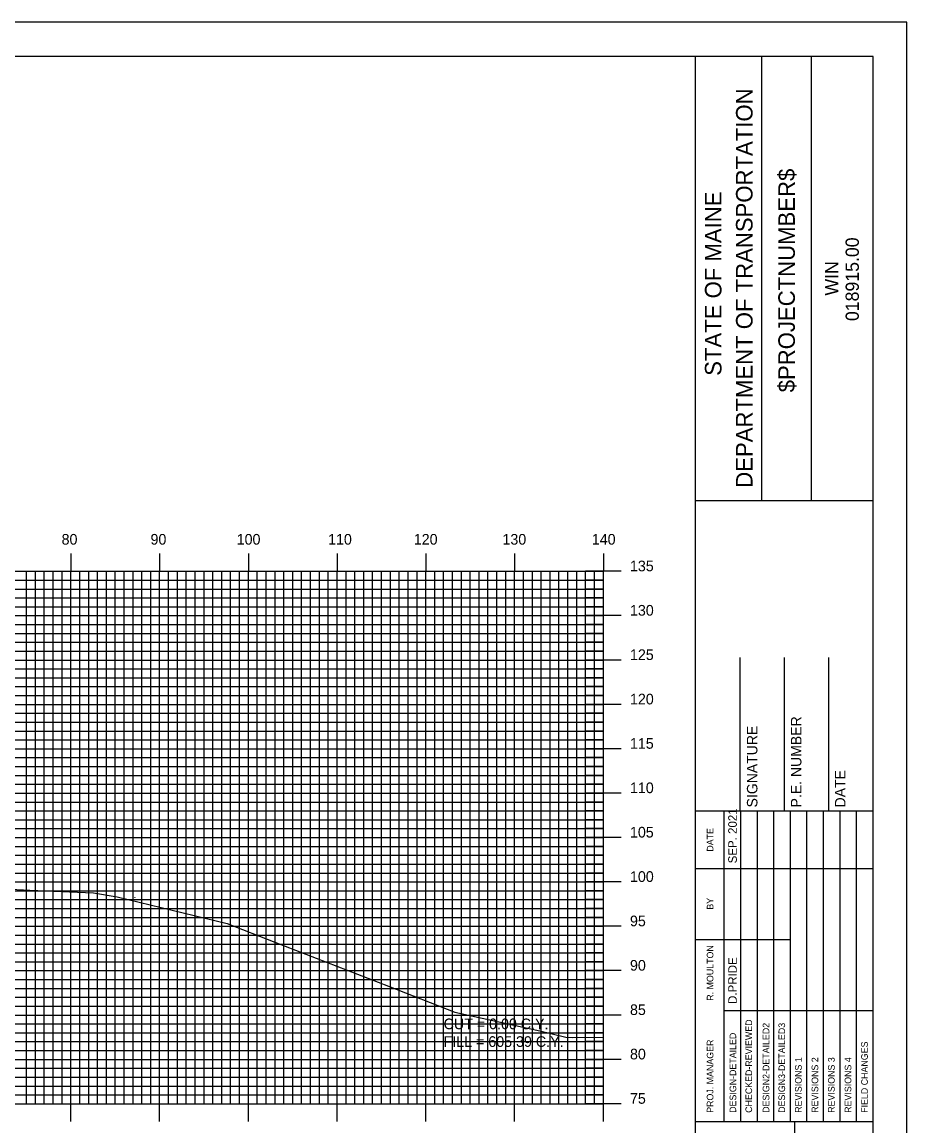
# Model space of a CAD drawing. Extents: x 857265 to 857608, y 364366 to 364586.
# Drawn here: x 857504.8 to 857604.5, y 364461.3 to 364585.7 of the extents above; entities that cross this region are included whole.
import ezdxf

# ---------------------------------------------------------------- set-up
doc = ezdxf.new("R2010")
doc.units = 0
for name, color, linetype in [('BORDER', 7, 'Continuous'), ('D_Text_Standard', 7, 'Continuous'), ('H_V ANNOTATION', 7, 'Continuous'), ('M_Utilities_Pole', 7, 'Continuous'), ('MAJOR', 7, 'Continuous'), ('MINOR', 7, 'Continuous'), ('PLOT BOUNDARY', 7, 'Continuous'), ('S_Roadway_Centerline', 7, 'Continuous')]:
    doc.layers.add(name, color=color, linetype=linetype)

msp = doc.modelspace()

# ---------------------------------------------------------------- linework, layer by layer
at = {"layer": 'BORDER'}
for p, q in [((857580.74, 364371.79), (857580.74, 364581.79)), ((857588.19, 364531.78), (857588.19, 364581.78)), ((857593.78, 364531.78), (857593.78, 364581.78)), ((857580.74, 364531.78), (857600.74, 364531.78)), ((857585.74, 364496.79), (857585.74, 364514.09)), ((857590.74, 364496.79), (857590.74, 364514.09)), ((857595.74, 364496.79), (857595.74, 364514.09)), ((857580.74, 364496.79), (857600.74, 364496.79)), ((857580.74, 364461.79), (857600.74, 364461.79)), ((857591.92, 364391.79), (857591.92, 364461.79))]:
    msp.add_line(p, q, dxfattribs=at)
msp.add_lwpolyline([(857280.74, 364371.79), (857600.74, 364371.79), (857600.74, 364581.79), (857280.74, 364581.79)], close=True, dxfattribs=at)
for points in [[(857583.97, 364490.29), (857583.97, 364496.79)], [(857585.83, 364461.8), (857585.83, 364496.79)], [(857587.69, 364496.79), (857587.69, 364461.8)], [(857589.56, 364461.8), (857589.56, 364496.79)], [(857591.42, 364461.8), (857591.42, 364496.79)], [(857593.28, 364461.8), (857593.28, 364496.79)], [(857595.15, 364461.8), (857595.15, 364496.79)], [(857597.01, 364461.8), (857597.01, 364496.79)], [(857598.87, 364461.8), (857598.87, 364496.79)], [(857583.97, 364461.8), (857583.97, 364495.38)], [(857580.74, 364490.29), (857600.74, 364490.29)], [(857580.74, 364482.29), (857583.97, 364482.29)], [(857583.97, 364482.29), (857591.42, 364482.29)], [(857583.97, 364474.29), (857600.74, 364474.29)]]:
    msp.add_lwpolyline(points, dxfattribs=at)
at = {"layer": 'M_Utilities_Pole'}
msp.add_line((857517.53, 364487.05), (857517.53, 364487.04), dxfattribs=at)
msp.add_circle((857517.53, 364487.05), 0.00417, dxfattribs=at)
at = {"layer": 'MAJOR'}
for p, q in [((857510.34, 364525.79), (857510.34, 364523.79)), ((857520.34, 364525.79), (857520.34, 364523.79)), ((857530.34, 364525.79), (857530.34, 364523.79)), ((857540.34, 364525.79), (857540.34, 364523.79)), ((857550.34, 364525.79), (857550.34, 364523.79)), ((857560.34, 364525.79), (857560.34, 364523.79)), ((857570.34, 364525.79), (857570.34, 364523.79)), ((857290.34, 364523.79), (857570.34, 364523.79)), ((857290.34, 364523.79), (857570.34, 364523.79)), ((857510.34, 364463.79), (857510.34, 364523.79)), ((857520.34, 364463.79), (857520.34, 364523.79)), ((857530.34, 364463.79), (857530.34, 364523.79)), ((857540.34, 364463.79), (857540.34, 364523.79)), ((857550.34, 364463.79), (857550.34, 364523.79)), ((857560.34, 364463.79), (857560.34, 364523.79)), ((857572.34, 364523.79), (857568.33, 364523.79)), ((857570.34, 364463.79), (857570.34, 364523.79)), ((857570.34, 364463.79), (857570.34, 364523.79)), ((857290.34, 364518.79), (857570.34, 364518.79)), ((857572.34, 364518.79), (857568.33, 364518.79)), ((857290.34, 364513.79), (857570.34, 364513.79)), ((857572.34, 364513.79), (857568.33, 364513.79)), ((857290.34, 364508.79), (857570.34, 364508.79)), ((857572.34, 364508.79), (857568.33, 364508.79)), ((857290.34, 364503.79), (857570.34, 364503.79)), ((857572.34, 364503.79), (857568.33, 364503.79)), ((857290.34, 364498.79), (857570.34, 364498.79)), ((857572.34, 364498.79), (857568.33, 364498.79)), ((857290.34, 364493.79), (857570.34, 364493.79)), ((857572.34, 364493.79), (857568.33, 364493.79)), ((857290.34, 364488.79), (857570.34, 364488.79)), ((857572.34, 364488.79), (857568.33, 364488.79)), ((857290.34, 364483.79), (857570.34, 364483.79)), ((857572.34, 364483.79), (857568.33, 364483.79)), ((857290.34, 364478.79), (857570.34, 364478.79)), ((857572.34, 364478.79), (857568.33, 364478.79)), ((857290.34, 364473.79), (857570.34, 364473.79)), ((857572.34, 364473.79), (857568.33, 364473.79)), ((857290.34, 364468.79), (857570.34, 364468.79)), ((857572.34, 364468.79), (857568.33, 364468.79)), ((857290.34, 364463.79), (857570.34, 364463.79)), ((857290.34, 364463.79), (857570.34, 364463.79)), ((857510.34, 364461.78), (857510.34, 364463.79)), ((857520.34, 364461.78), (857520.34, 364463.79)), ((857530.34, 364461.78), (857530.34, 364463.79)), ((857540.34, 364461.78), (857540.34, 364463.79)), ((857550.34, 364461.78), (857550.34, 364463.79)), ((857560.34, 364461.78), (857560.34, 364463.79)), ((857572.34, 364463.79), (857568.33, 364463.79)), ((857570.34, 364461.78), (857570.34, 364463.79))]:
    msp.add_line(p, q, dxfattribs=at)
at = {"layer": 'MINOR'}
for p, q in [((857290.34, 364522.79), (857570.34, 364522.79)), ((857505.34, 364463.79), (857505.34, 364523.79)), ((857506.34, 364463.79), (857506.34, 364523.79)), ((857507.34, 364463.79), (857507.34, 364523.79)), ((857508.34, 364463.79), (857508.34, 364523.79)), ((857509.34, 364463.79), (857509.34, 364523.79)), ((857511.34, 364463.79), (857511.34, 364523.79)), ((857512.34, 364463.79), (857512.34, 364523.79)), ((857513.34, 364463.79), (857513.34, 364523.79)), ((857514.34, 364463.79), (857514.34, 364523.79)), ((857515.34, 364463.79), (857515.34, 364523.79)), ((857516.34, 364463.79), (857516.34, 364523.79)), ((857517.34, 364463.79), (857517.34, 364523.79)), ((857518.34, 364463.79), (857518.34, 364523.79)), ((857519.34, 364463.79), (857519.34, 364523.79)), ((857521.34, 364463.79), (857521.34, 364523.79)), ((857522.34, 364463.79), (857522.34, 364523.79)), ((857523.34, 364463.79), (857523.34, 364523.79)), ((857524.34, 364463.79), (857524.34, 364523.79)), ((857525.34, 364463.79), (857525.34, 364523.79)), ((857526.34, 364463.79), (857526.34, 364523.79)), ((857527.34, 364463.79), (857527.34, 364523.79)), ((857528.34, 364463.79), (857528.34, 364523.79)), ((857529.34, 364463.79), (857529.34, 364523.79)), ((857531.34, 364463.79), (857531.34, 364523.79)), ((857532.34, 364463.79), (857532.34, 364523.79)), ((857533.34, 364463.79), (857533.34, 364523.79)), ((857534.34, 364463.79), (857534.34, 364523.79)), ((857535.34, 364463.79), (857535.34, 364523.79)), ((857536.34, 364463.79), (857536.34, 364523.79)), ((857537.34, 364463.79), (857537.34, 364523.79)), ((857538.34, 364463.79), (857538.34, 364523.79)), ((857539.34, 364463.79), (857539.34, 364523.79)), ((857541.34, 364463.79), (857541.34, 364523.79)), ((857542.34, 364463.79), (857542.34, 364523.79)), ((857543.34, 364463.79), (857543.34, 364523.79)), ((857544.34, 364463.79), (857544.34, 364523.79)), ((857545.34, 364463.79), (857545.34, 364523.79)), ((857546.34, 364463.79), (857546.34, 364523.79)), ((857547.34, 364463.79), (857547.34, 364523.79)), ((857548.34, 364463.79), (857548.34, 364523.79)), ((857549.34, 364463.79), (857549.34, 364523.79)), ((857551.34, 364463.79), (857551.34, 364523.79)), ((857552.34, 364463.79), (857552.34, 364523.79)), ((857553.34, 364463.79), (857553.34, 364523.79)), ((857554.34, 364463.79), (857554.34, 364523.79)), ((857555.34, 364463.79), (857555.34, 364523.79)), ((857556.34, 364463.79), (857556.34, 364523.79)), ((857557.34, 364463.79), (857557.34, 364523.79)), ((857558.34, 364463.79), (857558.34, 364523.79)), ((857559.34, 364463.79), (857559.34, 364523.79)), ((857561.34, 364463.79), (857561.34, 364523.79)), ((857562.34, 364463.79), (857562.34, 364523.79)), ((857563.34, 364463.79), (857563.34, 364523.79)), ((857564.34, 364463.79), (857564.34, 364523.79)), ((857565.34, 364463.79), (857565.34, 364523.79)), ((857566.34, 364463.79), (857566.34, 364523.79)), ((857567.34, 364463.79), (857567.34, 364523.79)), ((857570.34, 364522.79), (857568.33, 364522.79)), ((857568.34, 364463.79), (857568.34, 364523.79)), ((857569.34, 364463.79), (857569.34, 364523.79)), ((857290.34, 364521.79), (857570.34, 364521.79)), ((857570.34, 364521.79), (857568.33, 364521.79)), ((857290.34, 364520.79), (857570.34, 364520.79)), ((857570.34, 364520.79), (857568.33, 364520.79)), ((857290.34, 364519.79), (857570.34, 364519.79)), ((857570.34, 364519.79), (857568.33, 364519.79)), ((857290.34, 364517.79), (857570.34, 364517.79)), ((857570.34, 364517.79), (857568.33, 364517.79)), ((857290.34, 364516.79), (857570.34, 364516.79)), ((857570.34, 364516.79), (857568.33, 364516.79)), ((857290.34, 364515.79), (857570.34, 364515.79)), ((857570.34, 364515.79), (857568.33, 364515.79)), ((857290.34, 364514.79), (857570.34, 364514.79)), ((857570.34, 364514.79), (857568.33, 364514.79)), ((857290.34, 364512.79), (857570.34, 364512.79)), ((857570.34, 364512.79), (857568.33, 364512.79)), ((857290.34, 364511.79), (857570.34, 364511.79)), ((857570.34, 364511.79), (857568.33, 364511.79)), ((857290.34, 364510.79), (857570.34, 364510.79)), ((857570.34, 364510.79), (857568.33, 364510.79)), ((857290.34, 364509.79), (857570.34, 364509.79)), ((857570.34, 364509.79), (857568.33, 364509.79)), ((857290.34, 364507.79), (857570.34, 364507.79)), ((857570.34, 364507.79), (857568.33, 364507.79)), ((857290.34, 364506.79), (857570.34, 364506.79)), ((857570.34, 364506.79), (857568.33, 364506.79)), ((857290.34, 364505.79), (857570.34, 364505.79)), ((857570.34, 364505.79), (857568.33, 364505.79)), ((857290.34, 364504.79), (857570.34, 364504.79)), ((857570.34, 364504.79), (857568.33, 364504.79)), ((857290.34, 364502.79), (857570.34, 364502.79)), ((857570.34, 364502.79), (857568.33, 364502.79)), ((857290.34, 364501.79), (857570.34, 364501.79)), ((857570.34, 364501.79), (857568.33, 364501.79)), ((857290.34, 364500.79), (857570.34, 364500.79)), ((857570.34, 364500.79), (857568.33, 364500.79)), ((857290.34, 364499.79), (857570.34, 364499.79)), ((857570.34, 364499.79), (857568.33, 364499.79)), ((857290.34, 364497.79), (857570.34, 364497.79)), ((857570.34, 364497.79), (857568.33, 364497.79)), ((857290.34, 364496.79), (857570.34, 364496.79)), ((857570.34, 364496.79), (857568.33, 364496.79)), ((857290.34, 364495.79), (857570.34, 364495.79)), ((857570.34, 364495.79), (857568.33, 364495.79)), ((857290.34, 364494.79), (857570.34, 364494.79)), ((857570.34, 364494.79), (857568.33, 364494.79)), ((857290.34, 364492.79), (857570.34, 364492.79)), ((857570.34, 364492.79), (857568.33, 364492.79)), ((857290.34, 364491.79), (857570.34, 364491.79)), ((857570.34, 364491.79), (857568.33, 364491.79)), ((857290.34, 364490.79), (857570.34, 364490.79)), ((857570.34, 364490.79), (857568.33, 364490.79)), ((857290.34, 364489.79), (857570.34, 364489.79)), ((857570.34, 364489.79), (857568.33, 364489.79)), ((857290.34, 364487.79), (857570.34, 364487.79)), ((857570.34, 364487.79), (857568.33, 364487.79)), ((857290.34, 364486.79), (857570.34, 364486.79)), ((857570.34, 364486.79), (857568.33, 364486.79)), ((857290.34, 364485.79), (857570.34, 364485.79)), ((857570.34, 364485.79), (857568.33, 364485.79)), ((857290.34, 364484.79), (857570.34, 364484.79)), ((857570.34, 364484.79), (857568.33, 364484.79)), ((857290.34, 364482.79), (857570.34, 364482.79)), ((857570.34, 364482.79), (857568.33, 364482.79)), ((857290.34, 364481.79), (857570.34, 364481.79)), ((857570.34, 364481.79), (857568.33, 364481.79)), ((857290.34, 364480.79), (857570.34, 364480.79)), ((857570.34, 364480.79), (857568.33, 364480.79)), ((857290.34, 364479.79), (857570.34, 364479.79)), ((857570.34, 364479.79), (857568.33, 364479.79)), ((857290.34, 364477.79), (857570.34, 364477.79)), ((857570.34, 364477.79), (857568.33, 364477.79)), ((857290.34, 364476.79), (857570.34, 364476.79)), ((857570.34, 364476.79), (857568.33, 364476.79)), ((857290.34, 364475.79), (857570.34, 364475.79)), ((857570.34, 364475.79), (857568.33, 364475.79)), ((857290.34, 364474.79), (857570.34, 364474.79)), ((857570.34, 364474.79), (857568.33, 364474.79)), ((857290.34, 364472.79), (857570.34, 364472.79)), ((857290.34, 364471.79), (857570.34, 364471.79)), ((857570.34, 364472.79), (857568.33, 364472.79)), ((857570.34, 364471.79), (857568.33, 364471.79)), ((857290.34, 364470.79), (857570.34, 364470.79)), ((857570.34, 364470.79), (857568.33, 364470.79)), ((857290.34, 364469.79), (857570.34, 364469.79)), ((857570.34, 364469.79), (857568.33, 364469.79)), ((857290.34, 364467.79), (857570.34, 364467.79)), ((857290.34, 364466.79), (857570.34, 364466.79)), ((857570.34, 364467.79), (857568.33, 364467.79)), ((857570.34, 364466.79), (857568.33, 364466.79)), ((857290.34, 364465.79), (857570.34, 364465.79)), ((857570.34, 364465.79), (857568.33, 364465.79)), ((857290.34, 364464.79), (857570.34, 364464.79)), ((857570.34, 364464.79), (857568.33, 364464.79))]:
    msp.add_line(p, q, dxfattribs=at)
at = {"layer": 'PLOT BOUNDARY'}
msp.add_lwpolyline([(857264.55, 364365.67), (857604.55, 364365.67), (857604.55, 364585.67), (857264.55, 364585.67)], close=True, dxfattribs=at)
at = {"layer": 'S_Roadway_Centerline'}
msp.add_lwpolyline([(857498.39, 364488.22), (857505.71, 364487.85), (857512.88, 364487.57), (857515.56, 364487.11), (857527.94, 364484.12), (857533.32, 364481.98), (857546.14, 364477.05), (857553.6, 364474.1), (857563.17, 364472.02), (857566.1, 364471.29), (857566.85, 364471.27), (857568.31, 364471.28), (857570.34, 364471.25)], dxfattribs=at)

# ---------------------------------------------------------------- texts
at = {"layer": 'BORDER'}
for s, height, p in [('DEPARTMENT OF TRANSPORTATION', 1.8635, (857587.15, 364533.2)), ('$PROJECTNUMBER$', 1.8635, (857591.92, 364543.95)), ('STATE OF MAINE', 1.8635, (857583.65, 364545.81)), ('018915.00', 1.491, (857599.13, 364551.98)), ('WIN', 1.491, (857596.81, 364554.85)), ('P.E. NUMBER', 1.1811, (857592.66, 364497.18)), ('SIGNATURE', 1.181, (857587.7, 364497.18)), ('DATE', 1.181, (857597.62, 364497.18)), ('SEP. 2021', 0.969, (857585.38, 364490.88)), ('DATE', 0.743, (857582.74, 364492.2)), ('BY', 0.743, (857582.74, 364485.66)), ('R. MOULTON', 0.745, (857582.74, 364475.4)), ('D.PRIDE', 0.969, (857585.38, 364475.04)), ('CHECKED-REVIEWED', 0.7455, (857587.1, 364462.77)), ('DESIGN2-DETAILED2', 0.7455, (857589.04, 364462.77)), ('DESIGN3-DETAILED3', 0.7455, (857590.82, 364462.77)), ('DESIGN-DETAILED', 0.7455, (857585.31, 364462.77)), ('PROJ. MANAGER', 0.7455, (857582.74, 364462.77)), ('FIELD CHANGES', 0.7455, (857600.14, 364462.77)), ('REVISIONS 1', 0.7455, (857592.69, 364462.77)), ('REVISIONS 2', 0.7455, (857594.55, 364462.77)), ('REVISIONS 3', 0.7455, (857596.41, 364462.77)), ('REVISIONS 4', 0.7455, (857598.28, 364462.77))]:
    msp.add_text(s, height=height, rotation=90, dxfattribs=at).set_placement(p)
at = {"layer": 'D_Text_Standard'}
for s, p in [('CUT = 0.00 C.Y.', (857552.34, 364472.19)), ('FILL = 605.39 C.Y.', (857552.34, 364470.2))]:
    msp.add_text(s, height=1.2, dxfattribs=at).set_placement(p)
at = {"layer": 'H_V ANNOTATION'}
for s, p in [('80', (857509.29, 364526.79)), ('90', (857519.31, 364526.79)), ('100', (857529.02, 364526.79)), ('110', (857539.32, 364526.79)), ('120', (857548.98, 364526.79)), ('130', (857558.97, 364526.79)), ('140', (857569.04, 364526.79)), ('135', (857573.34, 364523.79)), ('130', (857573.34, 364518.79)), ('125', (857573.34, 364513.79)), ('120', (857573.34, 364508.79)), ('115', (857573.34, 364503.79)), ('110', (857573.34, 364498.79)), ('105', (857573.34, 364493.79)), ('100', (857573.34, 364488.79)), ('95', (857573.34, 364483.79)), ('90', (857573.34, 364478.79)), ('85', (857573.34, 364473.79)), ('80', (857573.34, 364468.79)), ('75', (857573.34, 364463.79))]:
    msp.add_text(s, height=1.2, dxfattribs=at).set_placement(p)

doc.saveas('drawing.dxf')
